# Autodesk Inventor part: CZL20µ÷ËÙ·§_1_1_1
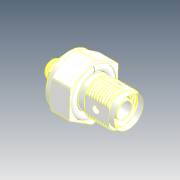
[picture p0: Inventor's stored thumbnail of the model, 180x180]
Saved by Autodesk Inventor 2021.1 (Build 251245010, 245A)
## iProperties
Created: 2021-05
Part Number: CZL20µ÷ËÙ·§_1_1_1
Material: Ogólny
Document SubType Name: Modeling
Designer: user
Density: 1 g/cm^3
Appearance: Domyślna
Author: user
Revision Number: ÈÎºÎ
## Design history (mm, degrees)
feature "NONE"
feature "Złożony1"
node "Bryła1"
body "Srf1"
